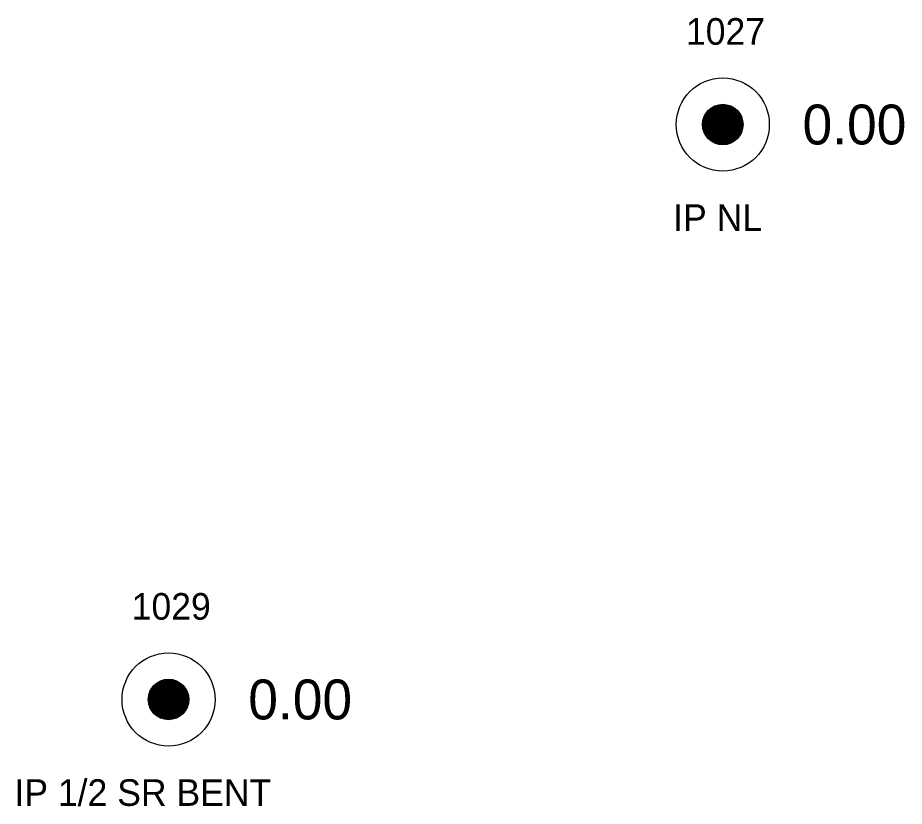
# Model space of a CAD drawing. Extents: x 1448136 to 1453623, y 1125056 to 1128842.
# Drawn here: x 1452993.4 to 1453026.74, y 1125124.1 to 1125153.75 of the extents above; entities that cross this region are included whole.
import ezdxf

# ---------------------------------------------------------------- set-up
doc = ezdxf.new("R2010")
doc.units = 0
for name, color, linetype in [('RD_EX_DV_Prop_txCode', 7, 'Continuous'), ('RD_EX_DV_PropPin', 7, 'Continuous'), ('RD_EX_TX_DV_Prop_ELEV', 7, 'Continuous'), ('RD_SMD_Locator', 7, 'Continuous')]:
    doc.layers.add(name, color=color, linetype=linetype)

msp = doc.modelspace()

# ---------------------------------------------------------------- linework, layer by layer
at = {"layer": 'RD_EX_DV_PropPin'}
for p, q in [((1453019.46, 1125149.122), (1453019.46, 1125150.342)), ((1453019.496, 1125149.097), (1453019.496, 1125150.366)), ((1453019.531, 1125149.075), (1453019.531, 1125150.388)), ((1453019.566, 1125149.056), (1453019.566, 1125150.407)), ((1453019.601, 1125149.039), (1453019.601, 1125150.424)), ((1453019.636, 1125149.024), (1453019.636, 1125150.439)), ((1453019.671, 1125149.011), (1453019.671, 1125150.452)), ((1453019.706, 1125149), (1453019.706, 1125150.463)), ((1453019.741, 1125148.991), (1453019.741, 1125150.472)), ((1453019.776, 1125148.984), (1453019.776, 1125150.48)), ((1453019.811, 1125148.978), (1453019.811, 1125150.485)), ((1453019.846, 1125148.974), (1453019.846, 1125150.489)), ((1453019.881, 1125148.971), (1453019.881, 1125150.492)), ((1453019.916, 1125148.971), (1453019.916, 1125150.493)), ((1453019.951, 1125148.971), (1453019.951, 1125150.492)), ((1453019.986, 1125148.974), (1453019.986, 1125150.489)), ((1453020.021, 1125148.978), (1453020.021, 1125150.485)), ((1453020.056, 1125148.984), (1453020.056, 1125150.48)), ((1453020.091, 1125148.991), (1453020.091, 1125150.472)), ((1453020.126, 1125149), (1453020.126, 1125150.463)), ((1453020.161, 1125149.011), (1453020.161, 1125150.452)), ((1453020.196, 1125149.024), (1453020.196, 1125150.439)), ((1453020.231, 1125149.039), (1453020.231, 1125150.424)), ((1453020.266, 1125149.056), (1453020.266, 1125150.407)), ((1453020.301, 1125149.075), (1453020.301, 1125150.388)), ((1453020.336, 1125149.097), (1453020.336, 1125150.366)), ((1453020.371, 1125149.122), (1453020.371, 1125150.342)), ((1453019.215, 1125149.434), (1453019.215, 1125150.03)), ((1453019.25, 1125149.362), (1453019.25, 1125150.101)), ((1453019.285, 1125149.305), (1453019.285, 1125150.158)), ((1453019.32, 1125149.258), (1453019.32, 1125150.206)), ((1453019.355, 1125149.217), (1453019.355, 1125150.247)), ((1453019.39, 1125149.181), (1453019.39, 1125150.282)), ((1453019.425, 1125149.15), (1453019.425, 1125150.314)), ((1453020.406, 1125149.15), (1453020.406, 1125150.314)), ((1453020.441, 1125149.181), (1453020.441, 1125150.282)), ((1453020.476, 1125149.217), (1453020.476, 1125150.247)), ((1453020.511, 1125149.258), (1453020.511, 1125150.206)), ((1453020.546, 1125149.305), (1453020.546, 1125150.158)), ((1453020.581, 1125149.362), (1453020.581, 1125150.101)), ((1453020.616, 1125149.434), (1453020.616, 1125150.03)), ((1453019.18, 1125149.536), (1453019.18, 1125149.928)), ((1453020.651, 1125149.536), (1453020.651, 1125149.928)), ((1452998.543, 1125127.567), (1452998.543, 1125128.668)), ((1452998.578, 1125127.535), (1452998.578, 1125128.7)), ((1452998.613, 1125127.508), (1452998.613, 1125128.727)), ((1452998.649, 1125127.483), (1452998.649, 1125128.752)), ((1452998.684, 1125127.461), (1452998.684, 1125128.774)), ((1452998.719, 1125127.442), (1452998.719, 1125128.793)), ((1452998.754, 1125127.425), (1452998.754, 1125128.81)), ((1452998.789, 1125127.41), (1452998.789, 1125128.825)), ((1452998.824, 1125127.397), (1452998.824, 1125128.838)), ((1452998.859, 1125127.386), (1452998.859, 1125128.849)), ((1452998.894, 1125127.377), (1452998.894, 1125128.858)), ((1452998.929, 1125127.369), (1452998.929, 1125128.866)), ((1452998.964, 1125127.364), (1452998.964, 1125128.871)), ((1452998.999, 1125127.36), (1452998.999, 1125128.875)), ((1452999.034, 1125127.357), (1452999.034, 1125128.878)), ((1452999.069, 1125127.356), (1452999.069, 1125128.879)), ((1452999.104, 1125127.357), (1452999.104, 1125128.878)), ((1452999.139, 1125127.36), (1452999.139, 1125128.875)), ((1452999.174, 1125127.364), (1452999.174, 1125128.871)), ((1452999.209, 1125127.369), (1452999.209, 1125128.866)), ((1452999.244, 1125127.377), (1452999.244, 1125128.858)), ((1452999.279, 1125127.386), (1452999.279, 1125128.849)), ((1452999.314, 1125127.397), (1452999.314, 1125128.838)), ((1452999.349, 1125127.41), (1452999.349, 1125128.825)), ((1452999.384, 1125127.425), (1452999.384, 1125128.81)), ((1452999.419, 1125127.442), (1452999.419, 1125128.793)), ((1452999.454, 1125127.461), (1452999.454, 1125128.774)), ((1452999.489, 1125127.483), (1452999.489, 1125128.752)), ((1452999.524, 1125127.508), (1452999.524, 1125128.727)), ((1452999.559, 1125127.535), (1452999.559, 1125128.7)), ((1452999.594, 1125127.567), (1452999.594, 1125128.668)), ((1452998.333, 1125127.921), (1452998.333, 1125128.314)), ((1452998.368, 1125127.82), (1452998.368, 1125128.415)), ((1452998.403, 1125127.748), (1452998.403, 1125128.487)), ((1452998.438, 1125127.691), (1452998.438, 1125128.544)), ((1452998.473, 1125127.643), (1452998.473, 1125128.592)), ((1452998.508, 1125127.602), (1452998.508, 1125128.633)), ((1452999.629, 1125127.602), (1452999.629, 1125128.633)), ((1452999.664, 1125127.643), (1452999.664, 1125128.592)), ((1452999.699, 1125127.691), (1452999.699, 1125128.544)), ((1452999.734, 1125127.748), (1452999.734, 1125128.487)), ((1452999.769, 1125127.82), (1452999.769, 1125128.415)), ((1452999.804, 1125127.921), (1452999.804, 1125128.314))]:
    msp.add_line(p, q, dxfattribs=at)
for centre, radius in [((1453019.916, 1125149.732), 1.75), ((1453019.916, 1125149.732), 0.761), ((1452999.069, 1125128.117), 1.75), ((1452999.069, 1125128.117), 0.761)]:
    msp.add_circle(centre, radius, dxfattribs=at)
at = {"layer": 'RD_SMD_Locator'}
for centre in [(1453019.916, 1125149.732), (1452999.069, 1125128.117)]:
    msp.add_circle(centre, 0.15, dxfattribs=at)

# ---------------------------------------------------------------- texts
at = {"layer": 'RD_EX_DV_Prop_txCode'}
for s, p in [('1027', (1453018.53, 1125152.732)), ('IP NL', (1453018.05, 1125145.732)), ('1029', (1452997.683, 1125131.118)), ('IP 1/2 SR BENT', (1452993.273, 1125124.118))]:
    msp.add_text(s, height=1, dxfattribs=at).set_placement(p)
at = {"layer": 'RD_EX_TX_DV_Prop_ELEV'}
for p in [(1453022.916, 1125148.982), (1453002.069, 1125127.368)]:
    msp.add_text('0.00', height=1.5, dxfattribs=at).set_placement(p)

doc.saveas('drawing.dxf')
